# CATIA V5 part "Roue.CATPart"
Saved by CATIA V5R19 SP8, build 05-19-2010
Part number: Roue
Bounding box of the stored display mesh (mm): x 450 to 549.954, y -79.933 to 319.933, z -509.933 to -110.067
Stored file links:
  C:\Users\ThinkMotion\Desktop\EU_thinkMotion\iao\IAO_MMS_Groupe3\rdalborgo\rdalborgo\Roue.CATPart
  C:\Users\ThinkMotion\Desktop\EU_thinkMotion\iao\IAO_MMS_Groupe3\rdalborgo\rdalborgo\rdalborgo.CATProduct
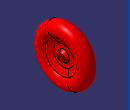
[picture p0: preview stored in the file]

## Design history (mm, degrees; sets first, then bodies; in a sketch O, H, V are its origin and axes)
External parameters (linked from other documents)
  `External.Axe inter diam` = 30 mm
Set1
  Plane1: linked copy from another document
  Line1: linked copy from another document
  Point1 "Ext roue": linked copy from another document
  Line2: linked copy from another document
Body1 (main body)
  Sketch1 on Plane1, origin (0, 120, 0), H (-1, 0, 0), V (0, 0, 1)
    arc A1 centre (-500, -160) radius 50 from (-450, -160) to (-530, -200) ccw
    point P1 (-500, -160)
    reference projected line E1 (-500, -310) -> (-500, -110) from Line1
    reference projected point E2 (-500, -110) from Point1
    point P2 (-530, -200)
    line L1 (-530, -200) -> (-510, -240)
    point P3 (-510, -240)
    line L2 (-510, -240) -> (-510, -270)
    point P4 (-510, -270)
    line L3 (-510, -270) -> (-530, -285)
    line L4 (-530, -285) -> (-530, -295)
    line L5 (-530, -295) -> (-470, -295)
    line L6 (-470, -295) -> (-470, -285)
    line L7 (-470, -285) -> (-490, -270)
    point P9 (-490, -270)
    line L8 (-490, -270) -> (-490, -240)
    point P10 (-490, -240)
    line L9 (-490, -240) -> (-470, -200)
    point P11 (-470, -200)
    reference projected line E3 (-480, -310) -> (-520, -310) from Line2
    reference projected line E4 (-500, -310) -> (-500, -110) from Line1
    arc A2 centre (-500, -160) radius 50 from (-470, -200) to (-450, -160) ccw
    point P12 (-450, -160)
    point P13 (-450, -160)
    radius A1 = 50
    distance L5 E3 = 15 {= `External.Axe inter diam` /2}
    length L6 = 10
    length L4 = 10
    distance L2 L8 = 20
    distance L8 E4 = 10
    distance P10 L5 = 55
    distance P3 L5 = 55
    distance P3 L4 = 20
    distance P4 L5 = 25
    distance P9 L5 = 25
    distance P2 L4 = 0
    distance L4 L6 = 60
    coincidence: P1 E1, A1 E2, P11 L6, P11 A1, A1 A2, P12 P13
    vertical: L2 V, L4 V, L6 V, L8 V
    horizontal: L5 H
  Shaft1: profile Sketch1, axis Line2, angle 360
